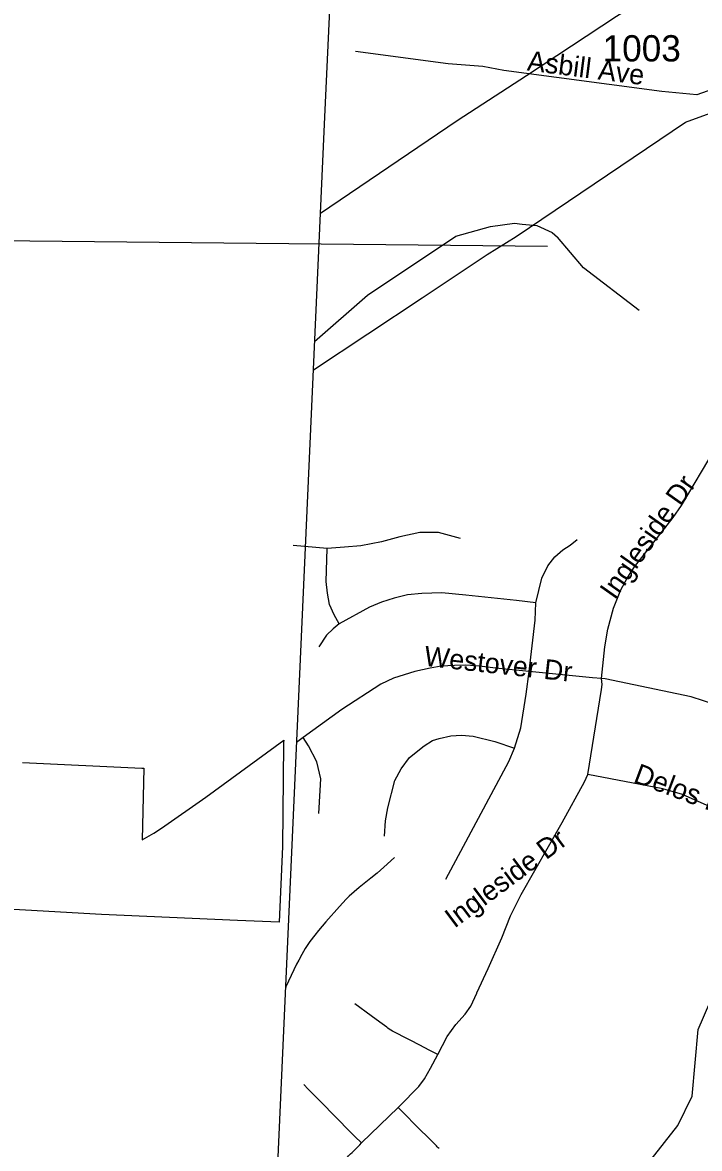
# Model space of a CAD drawing. Extents: x 1662474 to 1856135, y 779280 to 917889.
# Drawn here: x 1689866 to 1693083, y 816221 to 821576 of the extents above; entities that cross this region are included whole.
import ezdxf

# ---------------------------------------------------------------- set-up
doc = ezdxf.new("R2010")
doc.units = 0
for name, color, linetype in [('Exist Boundary Political City Limit New', 7, 'Continuous'), ('Exist Boundary Political CountyLine', 7, 'Continuous'), ('Exist Hydrographic Misc Water Feature', 7, 'Continuous'), ('Exist Road Non-System Type 51', 7, 'Continuous'), ('Exist Road Non-System Type 51 Label', 7, 'Continuous'), ('Exist Road Secondary Type 51 Number Label', 7, 'Continuous'), ('Exist Utilities Electrical Transmission Line', 7, 'Continuous'), ('Map Preparation Boundary City Limit Buffer Line', 7, 'Continuous'), ('Map Preparation Longitude Latitude Lines', 7, 'Continuous')]:
    doc.layers.add(name, color=color, linetype=linetype)

msp = doc.modelspace()

# ---------------------------------------------------------------- linework, layer by layer
at = {"layer": 'Exist Boundary Political City Limit New'}
msp.add_lwpolyline([(1689865.4, 818056.6), (1690432.4, 818029.7), (1690442.2, 818029.2), (1690433.4, 817689.4), (1690489.5, 817720.8), (1690525.8, 817744.6), (1690737.5, 817892.5), (1691107, 818162.6), (1691106.4, 818152), (1691105.9, 818144), (1691101.4, 817657.8), (1691085, 817297.8), (1690886.8, 817305.2), (1690240.8, 817333.9), (1689879.1, 817354.2), (1689615.5, 817369)], dxfattribs=at)
at = {"layer": 'Exist Boundary Political CountyLine'}
msp.add_lwpolyline([(1690989.8, 814167.1), (1691300.1, 821093.4), (1691456.7, 824436.5)], dxfattribs=at)
at = {"layer": 'Exist Hydrographic Misc Water Feature'}
for points in [[(1691924.7, 820560.7), (1692089.9, 820605.7), (1692203.5, 820621.7), (1692239.4, 820617.2), (1692309.6, 820610.3), (1692382.9, 820578.2), (1692407.7, 820555.9)], [(1691253.8, 820059.4), (1691504.9, 820279.1), (1691924.7, 820560.7)], [(1692795.9, 820206.9), (1692531.9, 820409.2), (1692407.7, 820555.9)], [(1692725.9, 816006.7), (1692979.9, 816329.8), (1693047.9, 816469.6), (1693075.9, 816787.4), (1693161.9, 816985.9), (1693381.9, 817332.6), (1693391.9, 817473.6), (1693451.9, 817616.8), (1693544.9, 817723.3), (1693603.9, 817797.5), (1693729.9, 817896.7), (1694030.9, 818041.6), (1694241.9, 818208), (1694309.9, 818347.8), (1694335.9, 818491.6), (1694313, 818666.1), (1694173.9, 818925), (1694184.9, 819125), (1694429.9, 819415.4), (1694506.9, 819620.6)], [(1691632.8, 817604.5), (1691582.7, 817558.8), (1691551, 817530.7), (1691521.6, 817507.5), (1691465.6, 817461.9), (1691418.5, 817420.9), (1691404.2, 817407.3), (1691371.7, 817371.8), (1691306.9, 817298.5), (1691272.4, 817257.4), (1691254.1, 817235.5), (1691230.7, 817205.7), (1691209.1, 817172.5), (1691192.7, 817144), (1691178.3, 817116.5), (1691168.2, 817097), (1691116.3, 816989.5), (1691115.9, 816982.3)]]:
    msp.add_lwpolyline(points, dxfattribs=at)
at = {"layer": 'Exist Road Non-System Type 51'}
for p, q in [((1691312.8, 819075.2), (1691152.1, 819089.6)), ((1691476.8, 816247.4), (1691650.8, 816415.9))]:
    msp.add_line(p, q, dxfattribs=at)
for points in [[(1693145.8, 821259.1), (1693070.1, 821232.4), (1692903.2, 821247.6), (1692153.4, 821348.9), (1692053.6, 821367.2), (1691889.1, 821379.9), (1691448.6, 821438.9)], [(1692616.6, 818456.2), (1692632.9, 818607.2), (1692647.4, 818690.9), (1692674.4, 818790.4), (1692709.6, 818878.4), (1692739.2, 818934.2), (1692773.9, 818987.2), (1692957.1, 819222.2), (1692996.9, 819278.6), (1693157.1, 819549.2), (1693168.1, 819577.8)], [(1691947.1, 819122.2), (1691843.1, 819150.2), (1691753.4, 819150.5), (1691659.4, 819130.2), (1691571, 819106.4), (1691474.1, 819087.5), (1691395.9, 819081.2), (1691312.8, 819075.2)], [(1691371, 818716.9), (1691347.4, 818758.7), (1691325.1, 818808.8), (1691314.9, 818862.6), (1691308.2, 818917.9), (1691312.8, 819075.2)], [(1692304.4, 818816.9), (1692333.4, 818933.4), (1692362.6, 818991.7), (1692394.9, 819035.5), (1692433.4, 819068.9), (1692467.9, 819090.9), (1692502.2, 819118.2)], [(1692304.4, 818816.9), (1692213.8, 818827.4), (1691972, 818852.6), (1691857.6, 818863.7), (1691763.6, 818860.8), (1691694.9, 818853.7), (1691632.4, 818838.7), (1691571, 818819.2), (1691514.9, 818795.1), (1691371, 818716.9)], [(1692273.1, 818489.9), (1692302.2, 818733.7), (1692304.4, 818816.9)], [(1691371, 818716.9), (1691341.9, 818693), (1691309.6, 818661.9), (1691273.1, 818607.5)], [(1692273.1, 818489.9), (1692112.8, 818506.2), (1692036.6, 818514.9), (1691973.1, 818520.1), (1691918, 818518.2), (1691855.5, 818514.9), (1691803, 818505.4), (1691730.4, 818489.9), (1691679.4, 818474.2), (1691629.2, 818458.7), (1691567.9, 818428.8), (1691383.6, 818309.6), (1691199.9, 818175.2)], [(1692203.2, 818125.4), (1692234.5, 818222.2), (1692258.6, 818382.5), (1692273.1, 818489.9)], [(1692616.6, 818456.2), (1692574.9, 818460), (1692273.1, 818489.9)], [(1692551.6, 817999.4), (1692617.9, 818404.6), (1692620.4, 818427.4), (1692616.6, 818456.2)], [(1693296.4, 818290.7), (1693278.4, 818293.9), (1693042.9, 818369.9), (1692634, 818454.4), (1692616.6, 818456.2)], [(1691199.9, 818175.2), (1691168.4, 818152.4)], [(1691273.9, 817814), (1691280.4, 817923), (1691283.9, 817979.4), (1691264.4, 818060.2), (1691225.1, 818136.6), (1691199.9, 818175.2)], [(1691586.5, 817706.4), (1691589.9, 817779.4), (1691602.2, 817841.9), (1691634.5, 817971), (1691664.6, 818026.4), (1691705.4, 818080.7), (1691774.9, 818136.4), (1691814, 818160.8), (1691845, 818171), (1691901.1, 818183.9), (1691952.4, 818186.8), (1692007.5, 818182.5), (1692109.6, 818156.6), (1692203.2, 818125.4)], [(1691878.1, 817502.2), (1692176.2, 818061.6), (1692203.2, 818125.4)], [(1691839.2, 816668.2), (1691883.6, 816753.9), (1691924.2, 816810.7), (1691969.4, 816860), (1691996.4, 816898.4), (1692024.9, 816959.5), (1692025.4, 816960.8), (1692079.1, 817076.5), (1692143.9, 817223.8), (1692184.1, 817326.9), (1692235.2, 817428.8), (1692430.4, 817771.2), (1692535.9, 817964.2), (1692551.6, 817999.4)], [(1693291.1, 817776), (1693001.4, 817905.1), (1692908, 817931.1), (1692551.6, 817999.4)], [(1691839.2, 816668.2), (1691798.6, 816689.2), (1691753.9, 816712), (1691707.8, 816735.9), (1691663.1, 816758.9), (1691661.6, 816759.5), (1691639.2, 816771), (1691623.8, 816779.4), (1691608.5, 816789.2), (1691602.2, 816793.6), (1691597.2, 816797.5), (1691564.1, 816821.9), (1691523, 816851.9), (1691444.5, 816909.9)], [(1691650.8, 816415.9), (1691657.6, 816422.8), (1691748.4, 816515.4), (1691776, 816551.9), (1691804.6, 816603.9), (1691839.2, 816668.2)], [(1691476.8, 816247.4), (1691445, 816278.7), (1691406.1, 816316.4), (1691371.8, 816353.2), (1691335.9, 816389.4), (1691300.1, 816425.6), (1691264.6, 816461.9), (1691243.6, 816482.9), (1691223, 816503.9), (1691202.2, 816524.9)], [(1691845.9, 816220.4), (1691841.4, 816224.6), (1691836.9, 816229), (1691832.6, 816233.8), (1691809.1, 816257.7), (1691737.1, 816329.6), (1691681, 816385.8), (1691650.8, 816415.9)], [(1691347.4, 816066.6), (1691372.4, 816126.2), (1691385.4, 816147.7), (1691389.4, 816153.4), (1691393.4, 816159.2), (1691397.2, 816164.5), (1691401.4, 816170), (1691405.9, 816175.2), (1691410.4, 816180.5), (1691415.1, 816185.5), (1691419.9, 816190.4), (1691424.9, 816195.2), (1691431.9, 816202.2), (1691467.9, 816238.8), (1691476.8, 816247.4)]]:
    msp.add_lwpolyline(points, dxfattribs=at)
at = {"layer": 'Exist Utilities Electrical Transmission Line'}
for points in [[(1691247.7, 819923.8), (1691765.1, 820266.6), (1692074.2, 820473), (1692211.2, 820558.9), (1693016.8, 821102.4), (1693308.1, 821209.1), (1694387.8, 822071.7), (1696193.9, 823484.3), (1697905.9, 824894), (1698412.5, 825294.6)], [(1691281.1, 820669.4), (1691930.6, 821110.2), (1692261, 821324.6), (1692688.2, 821606.1), (1693149.5, 821895.1), (1693508.3, 822133.3), (1693834.7, 822347.8), (1694257.8, 822617.2), (1694572.2, 822826), (1695106.1, 823170.1), (1695704.6, 823551.8), (1696125.7, 823829.2), (1696512.5, 824075.1), (1696907.6, 824334.9), (1697211.8, 824533.6), (1697578.5, 824773.6), (1697878.7, 824962.5), (1698227.3, 825188.7), (1698412.5, 825294.6)]]:
    msp.add_lwpolyline(points, dxfattribs=at)
at = {"layer": 'Map Preparation Boundary City Limit Buffer Line'}
msp.add_lwpolyline([(1689865.4, 818056.6), (1690432.4, 818029.7), (1690442.2, 818029.2), (1690433.4, 817689.4), (1690489.5, 817720.8), (1690525.8, 817744.6), (1690737.5, 817892.5), (1691107, 818162.6), (1691106.4, 818152), (1691105.9, 818144), (1691101.4, 817657.8), (1691085, 817297.8), (1690886.8, 817305.2), (1690240.8, 817333.9), (1689879.1, 817354.2), (1689615.5, 817369)], dxfattribs=at)
at = {"layer": 'Map Preparation Longitude Latitude Lines'}
msp.add_line((1687054.5, 820568.2), (1692361.2, 820512.5), dxfattribs=at)

# ---------------------------------------------------------------- texts
at = {"layer": 'Exist Road Non-System Type 51 Label'}
for s, rotation, p in [('Asbill Ave', 352.7545, (1692260.8, 821348.9)), ('Ingleside Dr', 54.8624, (1692679.9, 818826.8)), ('Westover Dr', 353.7696, (1691770.8, 818517.2)), ('Delos Pl', 339.4292, (1692764, 817965.2)), ('Ingleside Dr', 36.7861, (1691918.3, 817265.8))]:
    msp.add_text(s, height=95, rotation=rotation, dxfattribs=at).set_placement(p)
at = {"layer": 'Exist Road Secondary Type 51 Number Label'}
msp.add_text('1003', height=125, dxfattribs=at).set_placement((1692622.3, 821391.1))

doc.saveas('drawing.dxf')
